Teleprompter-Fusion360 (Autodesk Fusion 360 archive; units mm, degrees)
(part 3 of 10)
sketch "Skizze36" plane through (-14.9969, 0, 0) normal (-1, 0, 0) x axis (0, -1, 0)
  line L1 (-114.5768, 112.8622) -> (-167.9537, 59.4853)
  line L2 (-94.0916, 51) -> (-94.0916, 104.3769)
  line L3 (-159.4684, 39) -> (-106.0916, 39)
  line L4 (-169.9972, 16) -> (-214.6835, 16)
  line L5 (-164.3404, 0) -> (-164.3404, 12)
  line L6 (-130.1404, 0) -> (-164.3404, 0)
  line L7 (-130.1404, 12) -> (-130.1404, 0)
  line L8 (-95.9404, 12) -> (-130.1404, 12)
  line L9 (-95.9404, 0) -> (-95.9404, 12)
  line L10 (-61.7404, 0) -> (-95.9404, 0)
  line L11 (-61.7404, 12) -> (-61.7404, 0)
  line L12 (-27.5404, 12) -> (-61.7404, 12)
  line L13 (-27.5404, 0) -> (-27.5404, 12)
  line L14 (6.6596, 0) -> (-27.5404, 0)
  line L15 (6.6596, 15) -> (6.6596, 0)
  line L16 (-58.0916, 27) -> (-5.3404, 27)
  line L17 (-70.0916, 152.3769) -> (-70.0916, 39)
  line L18 (15.1449, 242.5839) -> (-66.5768, 160.8622)
  line L19 (18.6596, 263) -> (18.6596, 251.0692)
  line L20 (0.4576, 267) -> (14.6596, 267)
  line L21 (-121.7, 256.955) -> (-0.5298, 266.9593)
  line L22 (-126.9563, 256.521) -> (-123.6681, 256.7925)
  line L23 (-255.037, 12) -> (-136.7133, 249.9055)
  line L24 (-240.1877, 12) -> (-255.037, 12)
  line L25 (-240.1877, 0) -> (-240.1877, 12)
  line L26 (-220.3404, 0) -> (-240.1877, 0)
  line L27 (-220.3404, 12) -> (-220.3404, 0)
  line L28 (-121.7, 177.7124) -> (-121.7, 154.6976)
  line L29 (-113.9426, 181.955) -> (-117.4574, 181.955)
  line L30 (-109.7, 154.6976) -> (-109.7, 177.7124)
  line L31 (-117.4574, 150.455) -> (-113.9426, 150.455)
  line L32 (-117.4574, 213.455) -> (-113.9426, 213.455)
  line L33 (-121.7, 240.7124) -> (-121.7, 217.6976)
  line L34 (-113.9426, 244.955) -> (-117.4574, 244.955)
  line L35 (-109.7, 217.6976) -> (-109.7, 240.7124)
  line L36 (-45.7711, 251.1832) -> (-86.6874, 247.805)
  line L37 (-77.2147, 189.8223) -> (-36.2984, 230.7386)
  line L38 (-97.7, 235.8456) -> (-97.7, 198.3075)
  line L39 (-156.4445, 183.2864) -> (-195.6625, 104.4333)
  line L40 (-133.7, 138.3075) -> (-133.7, 177.9426)
  line L41 (-176.4327, 90.6042) -> (-137.2147, 129.8223)
  line L42 (-242.3091, 9.8787) -> (-240.1877, 12)
  line L43 (-237.1877, 12) -> (-240.1877, 12)
  line L44 (-128.0191, 9.8787) -> (-130.1404, 12)
  line L45 (-127.1404, 12) -> (-130.1404, 12)
  line L46 (-98.0617, 9.8787) -> (-95.9404, 12)
  line L47 (-92.9404, 12) -> (-95.9404, 12)
  line L48 (-59.6191, 9.8787) -> (-61.7404, 12)
  line L49 (-58.7404, 12) -> (-61.7404, 12)
  line L50 (-29.6617, 9.8787) -> (-27.5404, 12)
  line L51 (-24.5404, 12) -> (-27.5404, 12)
  circle C1 centre (-147.2404, 6) radius 1.5
  circle C2 centre (-78.8404, 6) radius 1.5
  circle C3 centre (-10.4404, 6) radius 1.5
  circle C4 centre (-230.2641, 6) radius 1.5
  arc A1 centre (-106.0916, 104.3769) radius 12 clockwise from (-114.5768, 112.8622) to (-94.0916, 104.3769)
  arc A2 centre (-106.0916, 51) radius 12 clockwise from (-94.0916, 51) to (-106.0916, 39)
  arc A3 centre (-159.4684, 51) radius 12 clockwise from (-159.4684, 39) to (-167.9537, 59.4853)
  arc A4 centre (-169.9972, 10) radius 6 clockwise from (-169.9972, 16) to (-164.3404, 12)
  arc A5 centre (-5.3404, 15) radius 12 clockwise from (-5.3404, 27) to (6.6596, 15)
  arc A6 centre (-58.0916, 39) radius 12 clockwise from (-58.0916, 27) to (-70.0916, 39)
  arc A7 centre (-58.0916, 152.3769) radius 12 clockwise from (-70.0916, 152.3769) to (-66.5768, 160.8622)
  arc A8 centre (6.6596, 251.0692) radius 12 clockwise from (18.6596, 251.0692) to (15.1449, 242.5839)
  arc A9 centre (14.6596, 263) radius 4 clockwise from (14.6596, 267) to (18.6596, 263)
  arc A10 centre (0.4576, 255) radius 12 clockwise from (-0.5298, 266.9593) to (0.4576, 267)
  arc A11 centre (-121.7, 244.955) radius 12 clockwise from (-123.6681, 256.7925) to (-121.7, 256.955)
  arc A12 centre (-125.9689, 244.5617) radius 12 clockwise from (-136.7133, 249.9055) to (-126.9563, 256.521)
  arc A13 centre (-214.6835, 10) radius 6 clockwise from (-220.3404, 12) to (-214.6835, 16)
  arc A14 centre (-119.5787, 179.8337) radius 3 clockwise from (-121.7, 177.7124) to (-117.4574, 181.955)
  arc A15 centre (-111.8213, 179.8337) radius 3 clockwise from (-113.9426, 181.955) to (-109.7, 177.7124)
  arc A16 centre (-111.8213, 152.5763) radius 3 clockwise from (-109.7, 154.6976) to (-113.9426, 150.455)
  arc A17 centre (-119.5787, 152.5763) radius 3 clockwise from (-117.4574, 150.455) to (-121.7, 154.6976)
  arc A18 centre (-119.5787, 215.5763) radius 3 clockwise from (-117.4574, 213.455) to (-121.7, 217.6976)
  arc A19 centre (-119.5787, 242.8337) radius 3 clockwise from (-121.7, 240.7124) to (-117.4574, 244.955)
  arc A20 centre (-111.8213, 242.8337) radius 3 clockwise from (-113.9426, 244.955) to (-109.7, 240.7124)
  arc A21 centre (-111.8213, 215.5763) radius 3 clockwise from (-109.7, 217.6976) to (-113.9426, 213.455)
  arc A22 centre (-85.7, 235.8456) radius 12 clockwise from (-97.7, 235.8456) to (-86.6874, 247.805)
  arc A23 centre (-44.7837, 239.2239) radius 12 clockwise from (-45.7711, 251.1832) to (-36.2984, 230.7386)
  arc A24 centre (-85.7, 198.3075) radius 12 clockwise from (-77.2147, 189.8223) to (-97.7, 198.3075)
  arc A25 centre (-184.918, 99.0895) radius 12 clockwise from (-176.4327, 90.6042) to (-195.6625, 104.4333)
  arc A26 centre (-145.7, 177.9426) radius 12 clockwise from (-156.4445, 183.2864) to (-133.7, 177.9426)
  arc A27 centre (-145.7, 138.3075) radius 12 clockwise from (-133.7, 138.3075) to (-137.2147, 129.8223)
  circle C5 centre (-29.6617, 9.8787) radius 3
  circle C6 centre (-59.6191, 9.8787) radius 3
  circle C7 centre (-98.0617, 9.8787) radius 3
  circle C8 centre (-128.0191, 9.8787) radius 3
  circle C9 centre (-242.3091, 9.8787) radius 3
  point P54 (-240.1877, 12)
  point P101 (-240.1877, 12)
  point P21 (-130.1404, 12)
  point P104 (-130.1404, 12)
  point P22 (-95.9404, 12)
  point P107 (-95.9404, 12)
  point P25 (-61.7404, 12)
  point P110 (-61.7404, 12)
  point P26 (-27.5404, 12)
  point P113 (-27.5404, 12)
  point P114 (-29.6617, 9.8787)
  point P116 (-29.6617, 9.8787)
  point P111 (-59.6191, 9.8787)
  point P117 (-59.6191, 9.8787)
  point P108 (-98.0617, 9.8787)
  point P118 (-98.0617, 9.8787)
  point P105 (-128.0191, 9.8787)
  point P119 (-128.0191, 9.8787)
  point P102 (-242.3091, 9.8787)
  point P120 (-242.3091, 9.8787)
  horizontal L43
  coincident P54 P101
  horizontal L45
  coincident P21 P104
  horizontal L47
  coincident P22 P107
  horizontal L49
  coincident P25 P110
  horizontal L51
  coincident P26 P113
  coincident P114 P116
  coincident P113 C5
  coincident P111 P117
  coincident P25 C6
  coincident P108 P118
  coincident P22 C7
  coincident P105 P119
  coincident P104 C8
  coincident P102 P120
  coincident P101 C9
  dimension "d208" angle L42 L43 = 135
  dimension "d209" distance P101 P102 = 3
  dimension "d210" distance P104 P105 = 3
  dimension "d211" angle L44 L45 = 45
  dimension "d212" angle L46 L47 = 135
  dimension "d213" distance P107 P108 = 3
  dimension "d214" angle L48 L49 = 45
  dimension "d215" distance P110 P111 = 3
  dimension "d216" angle L50 L51 = 135
  dimension "d217" distance P113 P114 = 3
extrude "Extrusion32" cut sketch "Skizze36" profile of L7 L8 L9 L11 L12 L13 L24 L25 C5 C6 C7 C8 C9 against normal blind 12
sketch "Skizze37" plane through (-14.9969, 0, 0) normal (-1, 0, 0) x axis (0, -1, 0)
  line L1 (-156.4445, 183.2864) -> (-195.6625, 104.4333)
  line L2 (-133.7, 138.3075) -> (-133.7, 177.9426)
  line L3 (-176.4327, 90.6042) -> (-137.2147, 129.8223)
  line L4 (-45.7711, 251.1832) -> (-86.6874, 247.805)
  line L5 (-77.2147, 189.8223) -> (-36.2984, 230.7386)
  line L6 (-97.7, 235.8456) -> (-97.7, 198.3075)
  line L7 (-117.4574, 213.455) -> (-113.9426, 213.455)
  line L8 (-121.7, 240.7124) -> (-121.7, 217.6976)
  line L9 (-113.9426, 244.955) -> (-117.4574, 244.955)
  line L10 (-109.7, 217.6976) -> (-109.7, 240.7124)
  line L11 (-121.7, 177.7124) -> (-121.7, 154.6976)
  line L12 (-113.9426, 181.955) -> (-117.4574, 181.955)
  line L13 (-109.7, 154.6976) -> (-109.7, 177.7124)
  line L14 (-117.4574, 150.455) -> (-113.9426, 150.455)
  line L15 (-114.5768, 112.8622) -> (-167.9537, 59.4853)
  line L16 (-94.0916, 51) -> (-94.0916, 104.3769)
  line L17 (-159.4684, 39) -> (-106.0916, 39)
  line L18 (-240.1877, 0) -> (-240.1877, 7.7574)
  line L19 (-220.3404, 0) -> (-240.1877, 0)
  line L20 (-220.3404, 12) -> (-220.3404, 0)
  line L21 (-169.9972, 16) -> (-214.6835, 16)
  line L22 (-164.3404, 0) -> (-164.3404, 12)
  line L23 (-130.1404, 0) -> (-164.3404, 0)
  line L24 (-130.1404, 7.7574) -> (-130.1404, 0)
  line L25 (-100.183, 12) -> (-125.8977, 12)
  line L26 (-95.9404, 0) -> (-95.9404, 7.7574)
  line L27 (-61.7404, 0) -> (-95.9404, 0)
  line L28 (-61.7404, 7.7574) -> (-61.7404, 0)
  line L29 (-31.783, 12) -> (-57.4977, 12)
  line L30 (-27.5404, 0) -> (-27.5404, 7.7574)
  line L31 (6.6596, 0) -> (-27.5404, 0)
  line L32 (6.6596, 15) -> (6.6596, 0)
  line L33 (-58.0916, 27) -> (-5.3404, 27)
  line L34 (-70.0916, 152.3769) -> (-70.0916, 39)
  line L35 (15.1449, 242.5839) -> (-66.5768, 160.8622)
  line L36 (18.6596, 263) -> (18.6596, 251.0692)
  line L37 (0.4576, 267) -> (14.6596, 267)
  line L38 (-121.7, 256.955) -> (-0.5298, 266.9593)
  line L39 (-126.9563, 256.521) -> (-123.6681, 256.7925)
  line L40 (-255.037, 12) -> (-136.7133, 249.9055)
  line L41 (-244.4304, 12) -> (-255.037, 12)
  line L42 (-121.7, 213.455) -> (-121.7, 244.955)
  line L43 (-109.7, 213.455) -> (-121.7, 213.455)
  line L44 (-109.7, 244.955) -> (-109.7, 213.455)
  line L45 (-121.7, 244.955) -> (-109.7, 244.955)
  line L46 (-109.7, 150.455) -> (-121.7, 150.455)
  line L47 (-109.7, 181.955) -> (-109.7, 150.455)
  line L48 (-121.7, 181.955) -> (-109.7, 181.955)
  line L49 (-121.7, 150.455) -> (-121.7, 181.955)
  line L50 (-109.7, 181.955) -> (-121.7, 213.455)
  line L51 (-121.7, 181.955) -> (-109.7, 213.455)
  arc A1 centre (-184.918, 99.0895) radius 12 clockwise from (-176.4327, 90.6042) to (-195.6625, 104.4333)
  arc A2 centre (-145.7, 177.9426) radius 12 clockwise from (-156.4445, 183.2864) to (-133.7, 177.9426)
  arc A3 centre (-145.7, 138.3075) radius 12 clockwise from (-133.7, 138.3075) to (-137.2147, 129.8223)
  arc A4 centre (-85.7, 235.8456) radius 12 clockwise from (-97.7, 235.8456) to (-86.6874, 247.805)
  arc A5 centre (-44.7837, 239.2239) radius 12 clockwise from (-45.7711, 251.1832) to (-36.2984, 230.7386)
  arc A6 centre (-85.7, 198.3075) radius 12 clockwise from (-77.2147, 189.8223) to (-97.7, 198.3075)
  arc A7 centre (-119.5787, 215.5763) radius 3 clockwise from (-117.4574, 213.455) to (-121.7, 217.6976)
  arc A8 centre (-119.5787, 242.8337) radius 3 clockwise from (-121.7, 240.7124) to (-117.4574, 244.955)
  arc A9 centre (-111.8213, 242.8337) radius 3 clockwise from (-113.9426, 244.955) to (-109.7, 240.7124)
  arc A10 centre (-111.8213, 215.5763) radius 3 clockwise from (-109.7, 217.6976) to (-113.9426, 213.455)
  arc A11 centre (-119.5787, 179.8337) radius 3 clockwise from (-121.7, 177.7124) to (-117.4574, 181.955)
  arc A12 centre (-111.8213, 179.8337) radius 3 clockwise from (-113.9426, 181.955) to (-109.7, 177.7124)
  arc A13 centre (-111.8213, 152.5763) radius 3 clockwise from (-109.7, 154.6976) to (-113.9426, 150.455)
  arc A14 centre (-119.5787, 152.5763) radius 3 clockwise from (-117.4574, 150.455) to (-121.7, 154.6976)
  arc A15 centre (-106.0916, 104.3769) radius 12 clockwise from (-114.5768, 112.8622) to (-94.0916, 104.3769)
  arc A16 centre (-106.0916, 51) radius 12 clockwise from (-94.0916, 51) to (-106.0916, 39)
  arc A17 centre (-159.4684, 51) radius 12 clockwise from (-159.4684, 39) to (-167.9537, 59.4853)
  circle C1 centre (-230.2641, 6) radius 1.5
  circle C2 centre (-10.4404, 6) radius 1.5
  circle C3 centre (-78.8404, 6) radius 1.5
  circle C4 centre (-147.2404, 6) radius 1.5
  arc A18 centre (-242.3091, 9.8787) radius 3 clockwise from (-244.4304, 12) to (-240.1877, 7.7574)
  arc A19 centre (-214.6835, 10) radius 6 clockwise from (-220.3404, 12) to (-214.6835, 16)
  arc A20 centre (-169.9972, 10) radius 6 clockwise from (-169.9972, 16) to (-164.3404, 12)
  arc A21 centre (-128.0191, 9.8787) radius 3 clockwise from (-130.1404, 7.7574) to (-125.8977, 12)
  arc A22 centre (-98.0617, 9.8787) radius 3 clockwise from (-100.183, 12) to (-95.9404, 7.7574)
  arc A23 centre (-59.6191, 9.8787) radius 3 clockwise from (-61.7404, 7.7574) to (-57.4977, 12)
  arc A24 centre (-29.6617, 9.8787) radius 3 clockwise from (-31.783, 12) to (-27.5404, 7.7574)
  arc A25 centre (-5.3404, 15) radius 12 clockwise from (-5.3404, 27) to (6.6596, 15)
  arc A26 centre (-58.0916, 39) radius 12 clockwise from (-58.0916, 27) to (-70.0916, 39)
  arc A27 centre (-58.0916, 152.3769) radius 12 clockwise from (-70.0916, 152.3769) to (-66.5768, 160.8622)
  arc A28 centre (6.6596, 251.0692) radius 12 clockwise from (18.6596, 251.0692) to (15.1449, 242.5839)
  arc A29 centre (14.6596, 263) radius 4 clockwise from (14.6596, 267) to (18.6596, 263)
  arc A30 centre (0.4576, 255) radius 12 clockwise from (-0.5298, 266.9593) to (0.4576, 267)
  arc A31 centre (-121.7, 244.955) radius 12 clockwise from (-123.6681, 256.7925) to (-121.7, 256.955)
  arc A32 centre (-125.9689, 244.5617) radius 12 clockwise from (-136.7133, 249.9055) to (-126.9563, 256.521)
  circle C5 centre (-115.7, 197.705) radius 1.5
  point P112 (-121.7, 213.455)
  point P119 (-121.7, 213.455)
  point P117 (-109.7, 181.955)
  point P120 (-109.7, 181.955)
  point P113 (-109.7, 213.455)
  point P121 (-109.7, 213.455)
  point P118 (-121.7, 181.955)
  point P122 (-121.7, 181.955)
  point P123 (-115.7, 197.705)
  coincident P112 P119
  coincident P117 P120
  coincident P113 P121
  coincident P118 P122
  midpoint L50 P123
  dimension "d220" diameter C5 = 3
extrude "Extrusion33" cut sketch "Skizze37" profile of C5 against normal blind 12
mirror "Spiegeln2" mirrorStitchTolerance 0.1
sketch "Skizze38" plane through (0, 0, 12) normal (0, 0, 1) x axis (-1, 0, 0)
  line L1 (14.9969, -164.3404) -> (0.9969, -164.3404)
  line L2 (14.9969, 6.6596) -> (14.9969, -164.3404)
  line L3 (-362.0031, 18.6596) -> (2.9969, 18.6596)
  line L4 (-374.0031, -168.3404) -> (-374.0031, 6.6596)
  line L5 (-364.0031, -168.3404) -> (-374.0031, -168.3404)
  line L6 (-360.0031, 0.1596) -> (-360.0031, -169.8683)
  line L7 (-3.5031, 4.6596) -> (-355.5031, 4.6596)
  line L8 (0.9969, -164.3404) -> (0.9969, 0.1596)
  line L9 (-374.0031, -27.5404) -> (-362.0031, -27.5404)
  line L10 (-362.0031, -27.5404) -> (-374.0031, -27.5404)
  line L11 (-362.0031, -61.7404) -> (-374.0031, -61.7404)
  line L12 (-374.0031, -61.7404) -> (-362.0031, -61.7404)
  line L13 (-362.0031, -130.1404) -> (-374.0031, -130.1404)
  line L14 (-374.0031, -130.1404) -> (-362.0031, -130.1404)
  line L15 (-374.0031, -95.9404) -> (-362.0031, -95.9404)
  line L16 (-362.0031, -95.9404) -> (-374.0031, -95.9404)
  line L17 (-362.0031, -164.3404) -> (-374.0031, -164.3404)
  line L18 (-374.0031, -164.3404) -> (-362.0031, -164.3404)
  line L19 (2.9969, -27.5404) -> (14.9969, -27.5404)
  line L20 (14.9969, -27.5404) -> (2.9969, -27.5404)
  line L21 (14.9969, -61.7404) -> (2.9969, -61.7404)
  line L22 (2.9969, -61.7404) -> (14.9969, -61.7404)
  line L23 (14.9969, -130.1404) -> (2.9969, -130.1404)
  line L24 (2.9969, -130.1404) -> (14.9969, -130.1404)
  line L25 (2.9969, -95.9404) -> (14.9969, -95.9404)
  line L26 (14.9969, -95.9404) -> (2.9969, -95.9404)
  line L27 (2.9969, -164.3404) -> (14.9969, -164.3404)
  line L28 (14.9969, -164.3404) -> (2.9969, -164.3404)
  line L29 (7.3469, -240.1877) -> (14.9969, -240.1877)
  line L30 (2.9969, -240.1877) -> (7.3469, -240.1877)
  line L31 (14.9969, -240.1877) -> (2.9969, -240.1877)
  line L32 (2.9969, -220.3404) -> (14.9969, -220.3404)
  line L33 (14.9969, -220.3404) -> (2.9969, -220.3404)
  line L34 (-362.0031, -220.3404) -> (-374.0031, -220.3404)
  line L35 (-374.0031, -220.3404) -> (-362.0031, -220.3404)
  line L36 (-374.0031, -240.1877) -> (-366.3531, -240.1877)
  line L37 (-362.0031, -240.1877) -> (-374.0031, -240.1877)
  line L38 (-366.3531, -240.1877) -> (-362.0031, -240.1877)
  line L39 (2.9969, -114.2) -> (2.9969, -117.2)
  line L40 (2.9969, -137.2147) -> (2.9969, -176.4327)
  line L41 (2.9969, -133.7) -> (2.9969, -137.2147)
  line L42 (2.9969, -133.7) -> (2.9969, -156.4445)
  line L43 (2.9969, -195.6625) -> (2.9969, -156.4445)
  line L44 (2.9969, -176.4327) -> (2.9969, -196.918)
  line L45 (2.9969, -77.2147) -> (2.9969, -97.7)
  line L46 (2.9969, -36.2984) -> (2.9969, -77.2147)
  line L47 (2.9969, -32.7837) -> (2.9969, -45.7711)
  line L48 (2.9969, -86.6874) -> (2.9969, -45.7711)
  line L49 (2.9969, -86.6874) -> (2.9969, -97.7)
  line L50 (2.9969, -113.9426) -> (2.9969, -117.4574)
  line L51 (2.9969, -108.8213) -> (2.9969, -113.9426)
  line L52 (2.9969, -108.8213) -> (2.9969, -113.9426)
  line L53 (2.9969, -117.4574) -> (2.9969, -113.9426)
  line L54 (2.9969, -117.4574) -> (2.9969, -122.5787)
  line L55 (2.9969, -117.4574) -> (2.9969, -122.5787)
  line L56 (2.9969, -117.4574) -> (2.9969, -122.5787)
  line L57 (2.9969, -113.9426) -> (2.9969, -117.4574)
  line L58 (2.9969, -108.8213) -> (2.9969, -113.9426)
  line L59 (2.9969, -108.8213) -> (2.9969, -113.9426)
  line L60 (2.9969, -117.4574) -> (2.9969, -113.9426)
  line L61 (2.9969, -117.4574) -> (2.9969, -122.5787)
  line L62 (2.9969, -239.478) -> (2.9969, -244.4304)
  line L63 (2.9969, -255.037) -> (2.9969, -244.4304)
  line L64 (2.9969, -136.7133) -> (2.9969, -255.037)
  line L65 (2.9969, -136.7133) -> (2.9969, -126.9563)
  line L66 (2.9969, -123.6681) -> (2.9969, -126.9563)
  line L67 (2.9969, -121.7) -> (2.9969, -123.6681)
  line L68 (2.9969, -0.5298) -> (2.9969, -121.7)
  line L69 (2.9969, 0.4576) -> (2.9969, -0.5298)
  line L70 (2.9969, 14.6596) -> (2.9969, 0.4576)
  line L71 (2.9969, 16.2993) -> (2.9969, 14.6596)
  line L72 (2.9969, -239.478) -> (2.9969, 16.2993)
  line L73 (-362.0031, -159.4684) -> (-362.0031, -106.0916)
  line L74 (-362.0031, -171.4684) -> (-362.0031, -159.4684)
  line L75 (-362.0031, -114.5768) -> (-362.0031, -167.9537)
  line L76 (-362.0031, -94.0916) -> (-362.0031, -114.5768)
  line L77 (-362.0031, -106.0916) -> (-362.0031, -94.0916)
  line L78 (-362.0031, -228.7641) -> (-362.0031, -231.7641)
  line L79 (-362.0031, -8.9404) -> (-362.0031, -11.9404)
  line L80 (-362.0031, -77.3404) -> (-362.0031, -80.3404)
  line L81 (-362.0031, -145.7404) -> (-362.0031, -148.7404)
  line L82 (-362.0031, -125.8977) -> (-362.0031, -131.0191)
  line L83 (-362.0031, -100.183) -> (-362.0031, -125.8977)
  line L84 (-362.0031, -95.0617) -> (-362.0031, -100.183)
  line L85 (-362.0031, -61.7404) -> (-362.0031, -95.9404)
  line L86 (-362.0031, -57.4977) -> (-362.0031, -62.6191)
  line L87 (-362.0031, -31.783) -> (-362.0031, -57.4977)
  line L88 (-362.0031, -26.6617) -> (-362.0031, -31.783)
  line L89 (-362.0031, 6.6596) -> (-362.0031, -27.5404)
  line L90 (-362.0031, 6.6596) -> (-362.0031, -5.3404)
  line L91 (-362.0031, -58.0916) -> (-362.0031, -5.3404)
  line L92 (-362.0031, -58.0916) -> (-362.0031, -70.0916)
  line L93 (-362.0031, -66.5768) -> (-362.0031, -70.0916)
  line L94 (-362.0031, 15.1449) -> (-362.0031, -66.5768)
  line L95 (-362.0031, 18.6596) -> (-362.0031, 15.1449)
  line L96 (-362.0031, -240.1877) -> (-362.0031, 18.6596)
  line L97 (-362.0031, -220.3404) -> (-362.0031, -240.1877)
  line L98 (-362.0031, -214.6835) -> (-362.0031, -220.3404)
  line L99 (-362.0031, -169.9972) -> (-362.0031, -214.6835)
  line L100 (-362.0031, -169.9972) -> (-362.0031, -164.3404)
  line L101 (-362.0031, -130.1404) -> (-362.0031, -164.3404)
  line L102 (14.9969, -117.2) -> (14.9969, -114.2)
  line L103 (14.9969, -176.4327) -> (14.9969, -196.918)
  line L104 (14.9969, -156.4445) -> (14.9969, -195.6625)
  line L105 (14.9969, -133.7) -> (14.9969, -156.4445)
  line L106 (14.9969, -137.2147) -> (14.9969, -133.7)
  line L107 (14.9969, -176.4327) -> (14.9969, -137.2147)
  line L108 (14.9969, -86.6874) -> (14.9969, -97.7)
  line L109 (14.9969, -45.7711) -> (14.9969, -86.6874)
  line L110 (14.9969, -32.7837) -> (14.9969, -45.7711)
  line L111 (14.9969, -77.2147) -> (14.9969, -36.2984)
  line L112 (14.9969, -97.7) -> (14.9969, -77.2147)
  line L113 (14.9969, -117.4574) -> (14.9969, -113.9426)
  line L114 (14.9969, -122.5787) -> (14.9969, -117.4574)
  line L115 (14.9969, -122.5787) -> (14.9969, -117.4574)
  line L116 (14.9969, -113.9426) -> (14.9969, -117.4574)
  line L117 (14.9969, -113.9426) -> (14.9969, -108.8213)
  line L118 (14.9969, -113.9426) -> (14.9969, -108.8213)
  line L119 (14.9969, -122.5787) -> (14.9969, -117.4574)
  line L120 (14.9969, -113.9426) -> (14.9969, -117.4574)
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extrude "Extrusion34" cut sketch "Skizze38" against normal blind 20
extrude "Extrusion35" cut of existing geometry blind -5
extrude "Extrusion36" cut of existing geometry blind -5
fillet "Abrundung11" radius 3
sketch "Skizze39" plane through (374.0031, 0, 0) normal (1, 0, 0) x axis (0, 1, 0)
  line L1 (137.2147, 129.8223) -> (176.4327, 90.6042)
  line L2 (133.7, 177.9426) -> (133.7, 138.3075)
  line L3 (195.6625, 104.4333) -> (156.4445, 183.2864)
  line L4 (97.7, 198.3075) -> (97.7, 235.8456)
  line L5 (36.2984, 230.7386) -> (77.2147, 189.8223)
  line L6 (86.6874, 247.805) -> (45.7711, 251.1832)
  line L7 (113.9426, 213.455) -> (117.4574, 213.455)
  line L8 (109.7, 240.7124) -> (109.7, 217.6976)
  line L9 (117.4574, 244.955) -> (113.9426, 244.955)
  line L10 (121.7, 217.6976) -> (121.7, 240.7124)
  line L11 (121.7, 154.6976) -> (121.7, 177.7124)
  line L12 (113.9426, 150.455) -> (117.4574, 150.455)
  line L13 (109.7, 177.7124) -> (109.7, 154.6976)
  line L14 (117.4574, 181.955) -> (113.9426, 181.955)
  line L15 (167.9537, 59.4853) -> (114.5768, 112.8622)
  line L16 (106.0916, 39) -> (159.4684, 39)
  line L17 (94.0916, 104.3769) -> (94.0916, 51)
  line L18 (255.037, 12) -> (244.4304, 12)
  line L19 (136.7133, 249.9055) -> (255.037, 12)
  line L20 (123.6681, 256.7925) -> (126.9563, 256.521)
  line L21
  line L22 (-14.6596, 267) -> (-0.4576, 267)
  line L23 (-18.6596, 251.0692) -> (-18.6596, 263)
  line L24 (66.5768, 160.8622) -> (-15.1449, 242.5839)
  line L25 (70.0916, 39) -> (70.0916, 152.3769)
  line L26 (5.3404, 27) -> (58.0916, 27)
  line L27 (-6.6596, 0) -> (-6.6596, 15)
  line L28 (27.5404, 0) -> (-6.6596, 0)
  line L29 (27.5404, 7.7574) -> (27.5404, 0)
  line L30 (57.4977, 12) -> (31.783, 12)
  line L31 (61.7404, 0) -> (61.7404, 7.7574)
  line L32 (95.9404, 0) -> (61.7404, 0)
  line L33 (95.9404, 7.7574) -> (95.9404, 0)
  line L34 (125.8977, 12) -> (100.183, 12)
  line L35 (130.1404, 0) -> (130.1404, 7.7574)
  line L36 (164.3404, 0) -> (130.1404, 0)
  line L37 (164.3404, 11.3932) -> (164.3404, 0)
  line L38 (214.6835, 16) -> (169.9972, 16)
  line L39 (220.3404, 0) -> (220.3404, 11.3932)
  line L40 (240.1877, 0) -> (220.3404, 0)
  line L41 (240.1877, 7.7574) -> (240.1877, 0)
  circle C1 centre (115.7, 197.705) radius 1.5
  arc A1 centre (184.918, 99.0895) radius 12 clockwise from (195.6625, 104.4333) to (176.4327, 90.6042)
  arc A2 centre (145.7, 138.3075) radius 12 clockwise from (137.2147, 129.8223) to (133.7, 138.3075)
  arc A3 centre (145.7, 177.9426) radius 12 clockwise from (133.7, 177.9426) to (156.4445, 183.2864)
  arc A4 centre (85.7, 235.8456) radius 12 clockwise from (86.6874, 247.805) to (97.7, 235.8456)
  arc A5 centre (85.7, 198.3075) radius 12 clockwise from (97.7, 198.3075) to (77.2147, 189.8223)
  arc A6 centre (44.7837, 239.2239) radius 12 clockwise from (36.2984, 230.7386) to (45.7711, 251.1832)
  arc A7 centre (111.8213, 215.5763) radius 3 clockwise from (113.9426, 213.455) to (109.7, 217.6976)
  arc A8 centre (111.8213, 242.8337) radius 3 clockwise from (109.7, 240.7124) to (113.9426, 244.955)
  arc A9 centre (119.5787, 242.8337) radius 3 clockwise from (117.4574, 244.955) to (121.7, 240.7124)
  arc A10 centre (119.5787, 215.5763) radius 3 clockwise from (121.7, 217.6976) to (117.4574, 213.455)
  arc A11 centre (119.5787, 152.5763) radius 3 clockwise from (121.7, 154.6976) to (117.4574, 150.455)
  arc A12 centre (111.8213, 152.5763) radius 3 clockwise from (113.9426, 150.455) to (109.7, 154.6976)
  arc A13 centre (111.8213, 179.8337) radius 3 clockwise from (109.7, 177.7124) to (113.9426, 181.955)
  arc A14 centre (119.5787, 179.8337) radius 3 clockwise from (117.4574, 181.955) to (121.7, 177.7124)
  arc A15 centre (159.4684, 51) radius 12 clockwise from (167.9537, 59.4853) to (159.4684, 39)
  arc A16 centre (106.0916, 51) radius 12 clockwise from (106.0916, 39) to (94.0916, 51)
  arc A17 centre (106.0916, 104.3769) radius 12 clockwise from (94.0916, 104.3769) to (114.5768, 112.8622)
  circle C2 centre (230.2641, 6) radius 1.5
  circle C3 centre (10.4404, 6) radius 1.5
  circle C4 centre (78.8404, 6) radius 1.5
  circle C5 centre (147.2404, 6) radius 1.5
  arc A18 centre (242.3091, 9.8787) radius 3 clockwise from (240.1877, 7.7574) to (244.4304, 12)
  arc A19 centre (125.9689, 244.5617) radius 12 clockwise from (126.9563, 256.521) to (136.7133, 249.9055)
  arc A20 centre (121.7, 244.955) radius 12 clockwise from (121.7, 256.955) to (123.6681, 256.7925)
  arc A21 centre (-0.4576, 255) radius 12 clockwise from (-0.4576, 267) to (0.5298, 266.9593)
  arc A22 centre (-14.6596, 263) radius 4 clockwise from (-18.6596, 263) to (-14.6596, 267)
  arc A23 centre (-6.6596, 251.0692) radius 12 clockwise from (-15.1449, 242.5839) to (-18.6596, 251.0692)
  arc A24 centre (58.0916, 152.3769) radius 12 clockwise from (66.5768, 160.8622) to (70.0916, 152.3769)
  arc A25 centre (58.0916, 39) radius 12 clockwise from (70.0916, 39) to (58.0916, 27)
  arc A26 centre (5.3404, 15) radius 12 clockwise from (-6.6596, 15) to (5.3404, 27)
  arc A27 centre (29.6617, 9.8787) radius 3 clockwise from (27.5404, 7.7574) to (31.783, 12)
  arc A28 centre (59.6191, 9.8787) radius 3 clockwise from (57.4977, 12) to (61.7404, 7.7574)
  arc A29 centre (98.0617, 9.8787) radius 3 clockwise from (95.9404, 7.7574) to (100.183, 12)
  arc A30 centre (128.0191, 9.8787) radius 3 clockwise from (125.8977, 12) to (130.1404, 7.7574)
  arc A31 centre (167.3404, 11.3932) radius 3 clockwise from (164.3404, 11.3932) to (164.6835, 12.7865)
  arc A32 centre (169.9972, 10) radius 6 clockwise from (164.6835, 12.7865) to (169.9972, 16)
  arc A33 centre (214.6835, 10) radius 6 clockwise from (214.6835, 16) to (219.9972, 12.7865)
  arc A34 centre (217.3404, 11.3932) radius 3 clockwise from (219.9972, 12.7865) to (220.3404, 11.3932)
extrude "Extrusion37" add sketch "Skizze39" profile of C5 against normal blind 12
sketch "Skizze40" plane through (-2.9969, 0, 0) normal (1, 0, 0) x axis (0, 1, 0)
  line L1 (106.0916, 39) -> (159.4684, 39)
  line L2 (94.0916, 104.3769) -> (94.0916, 51)
  line L3 (167.9537, 59.4853) -> (114.5768, 112.8622)
  line L4 (130.1404, 0) -> (130.1404, 7.7574)
  line L5 (164.3404, 0) -> (130.1404, 0)
  line L6 (164.3404, 11.3932) -> (164.3404, 0)
  line L7 (214.6835, 16) -> (169.9972, 16)
  line L8 (220.3404, 0) -> (220.3404, 11.3932)
  line L9 (240.1877, 0) -> (220.3404, 0)
  line L10 (240.1877, 3.939) -> (240.1877, 0)
  line L11 (-18.6596, 262.7863) -> (240.1877, 3.939)
  line L12 (-18.6596, 251.0692) -> (-18.6596, 262.7863)
  line L13 (66.5768, 160.8622) -> (-15.1449, 242.5839)
  line L14 (70.0916, 39) -> (70.0916, 152.3769)
  line L15 (5.3404, 27) -> (58.0916, 27)
  line L16 (-6.6596, 0) -> (-6.6596, 15)
  line L17 (27.5404, 0) -> (-6.6596, 0)
  line L18 (27.5404, 7.7574) -> (27.5404, 0)
  line L19 (57.4977, 12) -> (31.783, 12)
  line L20 (61.7404, 0) -> (61.7404, 7.7574)
  line L21 (95.9404, 0) -> (61.7404, 0)
  line L22 (95.9404, 7.7574) -> (95.9404, 0)
  line L23 (125.8977, 12) -> (100.183, 12)
  arc A1 centre (106.0916, 51) radius 12 clockwise from (106.0916, 39) to (94.0916, 51)
  arc A2 centre (106.0916, 104.3769) radius 12 clockwise from (94.0916, 104.3769) to (114.5768, 112.8622)
  arc A3 centre (159.4684, 51) radius 12 clockwise from (167.9537, 59.4853) to (159.4684, 39)
  circle C1 centre (230.2641, 6) radius 1.5
  circle C2 centre (10.4404, 6) radius 1.5
  circle C3 centre (78.8404, 6) radius 1.5
  circle C4 centre (147.2404, 6) radius 1.5
  arc A4 centre (128.0191, 9.8787) radius 3 clockwise from (125.8977, 12) to (130.1404, 7.7574)
  arc A5 centre (167.3404, 11.3932) radius 3 clockwise from (164.3404, 11.3932) to (164.6835, 12.7865)
  arc A6 centre (169.9972, 10) radius 6 clockwise from (164.6835, 12.7865) to (169.9972, 16)
  arc A7 centre (214.6835, 10) radius 6 clockwise from (214.6835, 16) to (219.9972, 12.7865)
  arc A8 centre (217.3404, 11.3932) radius 3 clockwise from (219.9972, 12.7865) to (220.3404, 11.3932)
  arc A9 centre (-6.6596, 251.0692) radius 12 clockwise from (-15.1449, 242.5839) to (-18.6596, 251.0692)
  arc A10 centre (58.0916, 152.3769) radius 12 clockwise from (66.5768, 160.8622) to (70.0916, 152.3769)
  arc A11 centre (58.0916, 39) radius 12 clockwise from (70.0916, 39) to (58.0916, 27)
  arc A12 centre (5.3404, 15) radius 12 clockwise from (-6.6596, 15) to (5.3404, 27)
  arc A13 centre (29.6617, 9.8787) radius 3 clockwise from (27.5404, 7.7574) to (31.783, 12)
  arc A14 centre (59.6191, 9.8787) radius 3 clockwise from (57.4977, 12) to (61.7404, 7.7574)
  arc A15 centre (98.0617, 9.8787) radius 3 clockwise from (95.9404, 7.7574) to (100.183, 12)
  circle C5 centre (147.2404, 6) radius 1.5
extrude "Extrusion38" add sketch "Skizze40" profile of C4 C5 against normal blind 12
sketch "Skizze41" plane through (360.0031, 0, 0) normal (-1, 0, 0) x axis (0, -1, 0)
  line L1 (-169.8683, 12) -> (0.1596, 12)
  line L2 (-169.8683, 4) -> (-169.8683, 12)
  line L3 (-150.3404, 4) -> (-169.8683, 4)
  line L4 (-169.8683, 4) -> (-150.3404, 4)
  line L5 (-169.8683, 12) -> (-169.8683, 4)
  line L6 (-150.3404, 12) -> (-169.8683, 12)
  line L7 (-150.3404, 4) -> (-150.3404, 12)
  line L8 (-150.3404, 9) -> (-150.3404, 4)
  line L9 (0.1596, 9) -> (-150.3404, 9)
  line L10 (0.1596, 12) -> (0.1596, 9)
  line L11 (-150.3404, 4) -> (-150.3404, 9)
  line L12 (-150.3404, 9) -> (-150.3404, 4)
  point P4 (-169.8683, 12)
  point P10 (-169.8683, 12)
  point P6 (-150.3404, 4)
  point P8 (-150.3404, 4)
  horizontal L4
  vertical L5
  horizontal L6
  vertical L7
  coincident P4 P10
  coincident P6 P8
extrude "Extrusion39" cut sketch "Skizze41" profile of L1 L2 L3 L4 L5 L6 L7 against normal blind 5
sketch "Skizze42" plane through (360.0031, 0, 0) normal (-1, 0, 0) x axis (0, -1, 0)
  line L1 (-221.8404, 12) -> (-216.8125, 12)
  line L2 (-221.8404, 4) -> (-221.8404, 12)
  line L3 (-216.8125, 4) -> (-221.8404, 4)
  line L4 (-216.8125, 12) -> (-216.8125, 4)
  line L5 (-226.3404, 4) -> (-226.3404, 12)
  line L6 (-226.3404, 12) -> (-226.3404, 4)
  line L7 (-216.8125, 4) -> (-226.3404, 4)
  line L8 (-216.8125, 12) -> (-216.8125, 4)
  line L9 (-226.3404, 12) -> (-216.8125, 12)
  line L10 (-226.3404, 4) -> (-226.3404, 12)
  point P2 (-216.8125, 12)
  point P10 (-216.8125, 12)
  point P7 (-226.3404, 4)
  point P8 (-226.3404, 4)
  horizontal L7
  vertical L8
  horizontal L9
  vertical L10
  coincident P2 P10
  coincident P7 P8
extrude "Extrusion40" cut sketch "Skizze42" profile of L1 L3 L4 L5 L6 L7 L8 L9 L10 against normal blind 4 and along normal blind 6
sketch "Skizze43" plane through (-0.9969, 0, 0) normal (1, 0, 0) x axis (0, 1, 0)
  line L1 (164.3404, 12) -> (164.3404, 4)
  line L2 (-0.1596, 12) -> (164.3404, 12)
  line L3 (-0.1596, 9) -> (-0.1596, 12)
  line L4 (150.3404, 9) -> (-0.1596, 9)
  line L5 (150.3404, 4) -> (150.3404, 9)
  line L6 (164.3404, 4) -> (150.3404, 4)
  line L7 (226.3404, 4) -> (226.3404, 12)
  line L8 (226.3404, 12) -> (226.3404, 4)
  line L9 (226.3404, 4) -> (221.8404, 4)
  line L10 (220.3404, 4) -> (221.8404, 4)
  line L11 (164.3404, 4) -> (220.3404, 4)
  line L12 (150.3404, 4) -> (164.3404, 4)
  line L13 (168.6835, 4) -> (150.3404, 4)
  line L14 (174.3404, 4) -> (168.6835, 4)
  line L15 (212.3404, 4) -> (174.3404, 4)
  line L16 (212.3404, 4) -> (217.9972, 4)
  line L17 (226.3404, 4) -> (217.9972, 4)
  line L18 (174.3404, 4) -> (190.3404, 4)
  line L19 (174.3404, 4) -> (162.3404, 4)
  line L20 (174.3404, 4) -> (162.3404, 4)
  line L21 (190.3404, 4) -> (174.3404, 4)
  line L22 (202.3404, 4) -> (190.3404, 4)
  line L23 (202.3404, 4) -> (190.3404, 4)
  line L24 (202.3404, 4) -> (190.3404, 4)
  line L25 (174.3404, 4) -> (190.3404, 4)
  line L26 (174.3404, 4) -> (162.3404, 4)
  line L27 (174.3404, 4) -> (162.3404, 4)
  line L28 (190.3404, 4) -> (174.3404, 4)
  line L29 (202.3404, 4) -> (190.3404, 4)
  line L30 (226.3404, 4) -> (150.3404, 4)
  line L31 (226.3404, 12) -> (226.3404, 4)
  line L32 (150.3404, 12) -> (226.3404, 12)
  line L33 (150.3404, 4) -> (150.3404, 12)
  point P8 (226.3404, 12)
  point P24 (226.3404, 12)
  point P14 (150.3404, 4)
  point P22 (150.3404, 4)
  horizontal L30
  vertical L31
  horizontal L32
  vertical L33
  coincident P8 P24
  coincident P14 P22
extrude "Extrusion41" cut sketch "Skizze43" profile of L1 L2 L5 L6 L7 L8 L9 L10 L11 L12 L13 L14 L15 L16 L17 L18 L19 L20 L21 L22 L23 L24 L25 L26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 along normal blind 10 and against normal blind 10
sketch "Skizze44" plane through (0, 0, 4) normal (0, 0, 1) x axis (-1, 0, 0)
  line L1 (-155.5031, -202.3404) -> (-71.0031, -202.3404)
  line L2 (-167.5031, -174.3404) -> (-167.5031, -190.3404)
  line L3 (-71.0031, -162.3404) -> (-155.5031, -162.3404)
  line L4 (-59.0031, -190.3404) -> (-59.0031, -174.3404)
  line L5 (-300.0031, -174.3404) -> (-300.0031, -190.3404)
  line L6 (-203.5031, -162.3404) -> (-288.0031, -162.3404)
  line L7 (-191.5031, -190.3404) -> (-191.5031, -174.3404)
  line L8 (-288.0031, -202.3404) -> (-203.5031, -202.3404)
  line L9 (-362.0031, -150.3404) -> (2.9969, -150.3404)
  line L10 (-362.0031, -168.6835) -> (-362.0031, -150.3404)
  line L11 (-358.0031, -212.3404) -> (-358.0031, -174.3404)
  line L12 (-362.0031, -226.3404) -> (-362.0031, -217.9972)
  line L13 (2.9969, -226.3404) -> (-362.0031, -226.3404)
  line L14 (2.9969, -220.3404) -> (2.9969, -226.3404)
  line L15 (14.9969, -220.3404) -> (2.9969, -220.3404)
  line L16 (14.9969, -164.3404) -> (14.9969, -220.3404)
  line L17 (2.9969, -164.3404) -> (14.9969, -164.3404)
  line L18 (2.9969, -150.3404) -> (2.9969, -164.3404)
  line L19 (14.9969, -220.3404) -> (2.9969, -220.3404)
  line L20 (14.9969, -164.3404) -> (14.9969, -220.3404)
  line L21 (2.9969, -164.3404) -> (14.9969, -164.3404)
  line L22 (2.9969, -220.3404) -> (2.9969, -164.3404)
  arc A1 centre (-155.5031, -190.3404) radius 12 clockwise from (-155.5031, -202.3404) to (-167.5031, -190.3404)
  arc A2 centre (-155.5031, -174.3404) radius 12 clockwise from (-167.5031, -174.3404) to (-155.5031, -162.3404)
  arc A3 centre (-71.0031, -174.3404) radius 12 clockwise from (-71.0031, -162.3404) to (-59.0031, -174.3404)
  arc A4 centre (-71.0031, -190.3404) radius 12 clockwise from (-59.0031, -190.3404) to (-71.0031, -202.3404)
  arc A5 centre (-288.0031, -174.3404) radius 12 clockwise from (-300.0031, -174.3404) to (-288.0031, -162.3404)
  arc A6 centre (-203.5031, -174.3404) radius 12 clockwise from (-203.5031, -162.3404) to (-191.5031, -174.3404)
  arc A7 centre (-203.5031, -190.3404) radius 12 clockwise from (-191.5031, -190.3404) to (-203.5031, -202.3404)
  arc A8 centre (-288.0031, -190.3404) radius 12 clockwise from (-288.0031, -202.3404) to (-300.0031, -190.3404)
  arc A9 centre (-364.0031, -174.3404) radius 6 clockwise from (-362.0031, -168.6835) to (-358.0031, -174.3404)
  arc A10 centre (-364.0031, -212.3404) radius 6 clockwise from (-358.0031, -212.3404) to (-362.0031, -217.9972)
  point P38 (14.9969, -164.3404)
  point P42 (14.9969, -164.3404)
  point P36 (2.9969, -220.3404)
  point P40 (2.9969, -220.3404)
  horizontal L19
  vertical L20
  horizontal L21
  vertical L22
  coincident P38 P42
  coincident P36 P40
extrude "Extrusion42" cut sketch "Skizze44" profile of L15 L16 L17 L19 L20 L21 L22 against normal blind 10
sketch "Skizze45" plane through (0, 0, 0) normal (0, 0, -1) x axis (1, 0, 0)
  line L1 (47.0031, -126.3404) -> (155.5031, -126.3404)
  line L2 (35.0031, -31.3404) -> (35.0031, -114.3404)
  line L3 (155.5031, -19.3404) -> (47.0031, -19.3404)
  line L4 (167.5031, -114.3404) -> (167.5031, -31.3404)
  line L5 (71.0031, -202.3404) -> (155.5031, -202.3404)
  line L6 (59.0031, -174.3404) -> (59.0031, -190.3404)
  line L7 (155.5031, -162.3404) -> (71.0031, -162.3404)
  line L8 (167.5031, -190.3404) -> (167.5031, -174.3404)
  line L9 (191.5031, -31.3404) -> (191.5031, -114.3404)
  line L10 (312.0031, -19.3404) -> (203.5031, -19.3404)
  line L11 (324.0031, -114.3404) -> (324.0031, -31.3404)
  line L12 (203.5031, -126.3404) -> (312.0031, -126.3404)
  line L13 (300.0031, -190.3404) -> (300.0031, -174.3404)
  line L14 (203.5031, -202.3404) -> (288.0031, -202.3404)
  line L15 (191.5031, -174.3404) -> (191.5031, -190.3404)
  line L16 (288.0031, -162.3404) -> (203.5031, -162.3404)
  line L17 (-2.9969, -240.1877) -> (-2.9969, -130.1404)
  line L18 (-14.9969, -240.1877) -> (-2.9969, -240.1877)
  line L19 (-14.9969, -255.3404) -> (-14.9969, -240.1877)
  line L20 (374.0031, -255.3404) -> (-14.9969, -255.3404)
  line L21 (374.0031, -240.1877) -> (374.0031, -255.3404)
  line L22 (362.0031, -240.1877) -> (374.0031, -240.1877)
  line L23 (362.0031, -217.9972) -> (362.0031, -240.1877)
  line L24 (358.0031, -174.3404) -> (358.0031, -212.3404)
  line L25 (362.0031, -130.1404) -> (362.0031, -168.6835)
  line L26 (374.0031, -130.1404) -> (362.0031, -130.1404)
  line L27 (374.0031, -95.9404) -> (374.0031, -130.1404)
  line L28 (362.0031, -95.9404) -> (374.0031, -95.9404)
  line L29 (362.0031, -61.7404) -> (362.0031, -95.9404)
  line L30 (374.0031, -61.7404) -> (362.0031, -61.7404)
  line L31 (374.0031, -27.5404) -> (374.0031, -61.7404)
  line L32 (362.0031, -27.5404) -> (374.0031, -27.5404)
  line L33 (362.0031, 6.6596) -> (362.0031, -27.5404)
  line L34 (374.0031, 6.6596) -> (362.0031, 6.6596)
  line L35 (-2.9969, 18.6596) -> (362.0031, 18.6596)
  line L36 (-2.9969, 6.6596) -> (-14.9969, 6.6596)
  line L37 (-2.9969, -27.5404) -> (-2.9969, 6.6596)
  line L38 (-14.9969, -27.5404) -> (-2.9969, -27.5404)
  line L39 (-14.9969, -61.7404) -> (-14.9969, -27.5404)
  line L40 (-2.9969, -61.7404) -> (-14.9969, -61.7404)
  line L41 (-2.9969, -95.9404) -> (-2.9969, -61.7404)
  line L42 (-14.9969, -95.9404) -> (-2.9969, -95.9404)
  line L43 (-14.9969, -130.1404) -> (-14.9969, -95.9404)
  line L44 (-2.9969, -130.1404) -> (-14.9969, -130.1404)
  line L45 (374.0031, -130.1404) -> (362.0031, -95.9404)
  line L46 (362.0031, -130.1404) -> (374.0031, -95.9404)
  line L47 (-2.9969, -130.1404) -> (-14.9969, -95.9404)
  line L48 (-14.9969, -130.1404) -> (-2.9969, -95.9404)
  arc A1 centre (47.0031, -114.3404) radius 12 clockwise from (47.0031, -126.3404) to (35.0031, -114.3404)
  arc A2 centre (47.0031, -31.3404) radius 12 clockwise from (35.0031, -31.3404) to (47.0031, -19.3404)
  arc A3 centre (155.5031, -31.3404) radius 12 clockwise from (155.5031, -19.3404) to (167.5031, -31.3404)
  arc A4 centre (155.5031, -114.3404) radius 12 clockwise from (167.5031, -114.3404) to (155.5031, -126.3404)
  arc A5 centre (71.0031, -190.3404) radius 12 clockwise from (71.0031, -202.3404) to (59.0031, -190.3404)
  arc A6 centre (71.0031, -174.3404) radius 12 clockwise from (59.0031, -174.3404) to (71.0031, -162.3404)
  arc A7 centre (155.5031, -174.3404) radius 12 clockwise from (155.5031, -162.3404) to (167.5031, -174.3404)
  arc A8 centre (155.5031, -190.3404) radius 12 clockwise from (167.5031, -190.3404) to (155.5031, -202.3404)
  arc A9 centre (203.5031, -31.3404) radius 12 clockwise from (191.5031, -31.3404) to (203.5031, -19.3404)
  arc A10 centre (312.0031, -31.3404) radius 12 clockwise from (312.0031, -19.3404) to (324.0031, -31.3404)
  arc A11 centre (312.0031, -114.3404) radius 12 clockwise from (324.0031, -114.3404) to (312.0031, -126.3404)
  arc A12 centre (203.5031, -114.3404) radius 12 clockwise from (203.5031, -126.3404) to (191.5031, -114.3404)
  arc A13 centre (288.0031, -190.3404) radius 12 clockwise from (300.0031, -190.3404) to (288.0031, -202.3404)
  arc A14 centre (203.5031, -190.3404) radius 12 clockwise from (203.5031, -202.3404) to (191.5031, -190.3404)
  arc A15 centre (203.5031, -174.3404) radius 12 clockwise from (191.5031, -174.3404) to (203.5031, -162.3404)
  arc A16 centre (288.0031, -174.3404) radius 12 clockwise from (288.0031, -162.3404) to (300.0031, -174.3404)
  arc A17 centre (364.0031, -212.3404) radius 6 clockwise from (362.0031, -217.9972) to (358.0031, -212.3404)
  arc A18 centre (364.0031, -174.3404) radius 6 clockwise from (358.0031, -174.3404) to (362.0031, -168.6835)
  arc A19 centre (362.0031, 6.6596) radius 12 clockwise from (362.0031, 18.6596) to (374.0031, 6.6596)
  arc A20 centre (-2.9969, 6.6596) radius 12 clockwise from (-14.9969, 6.6596) to (-2.9969, 18.6596)
  circle C1 centre (368.0031, -113.0404) radius 1.5
  circle C2 centre (-8.9969, -113.0404) radius 1.5
  point P66 (362.0031, -95.9404)
  point P84 (362.0031, -95.9404)
  point P64 (374.0031, -130.1404)
  point P85 (374.0031, -130.1404)
  point P65 (374.0031, -95.9404)
  point P86 (374.0031, -95.9404)
  point P63 (362.0031, -130.1404)
  point P87 (362.0031, -130.1404)
  point P82 (-14.9969, -95.9404)
  point P88 (-14.9969, -95.9404)
  point P50 (-2.9969, -130.1404)
  point P89 (-2.9969, -130.1404)
  point P81 (-2.9969, -95.9404)
  point P90 (-2.9969, -95.9404)
  point P83 (-14.9969, -130.1404)
  point P91 (-14.9969, -130.1404)
  point P92 (368.0031, -113.0404)
  point P93 (-8.9969, -113.0404)
  coincident P66 P84
  coincident P64 P85
  coincident P65 P86
  coincident P63 P87
  coincident P82 P88
  coincident P50 P89
  coincident P81 P90
  coincident P83 P91
  midpoint L46 P92
  midpoint L47 P93
  dimension "d249" diameter C1 = 3
  dimension "d250" diameter C2 = 3
extrude "Extrusion43" cut sketch "Skizze45" profile of C1 C2 against normal blind 12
